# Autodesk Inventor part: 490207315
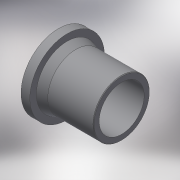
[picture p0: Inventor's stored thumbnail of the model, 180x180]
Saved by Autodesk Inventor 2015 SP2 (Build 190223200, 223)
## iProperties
Created: 2017-07
Part Number: 490207315
Material: Generic
Description: Stub Flange 315
Document SubType Name: Modeling
Designer: Кирилл
Mass: 7867.44 g
Surface Area: 5540.86 cm^2
Volume: 7867.44 cm^3
Density: 1 g/cm^3
Appearance: Default
Author: Кирилл
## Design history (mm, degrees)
derived "490207.ipt"
feature "Solid1::490207.ipt"
tag "TaggingFeature1"
body "Solid1"
other parameters: "d0" = 238, "d1" = 335, "d2" = 315, "d3" = 252, "d5" = 35, "d16" = 315, "d17" = 6.3, "d18" = 6.3, "d19" = 6.3, "d21" = 6.3, "d24" = 6.3, "d25" = 6.3, "d26" = 3.15, "d27" = 0, "d32" = 3.15, "d_" = 315, "L_" = 238, "D_1" = 335, "a_" = 35
